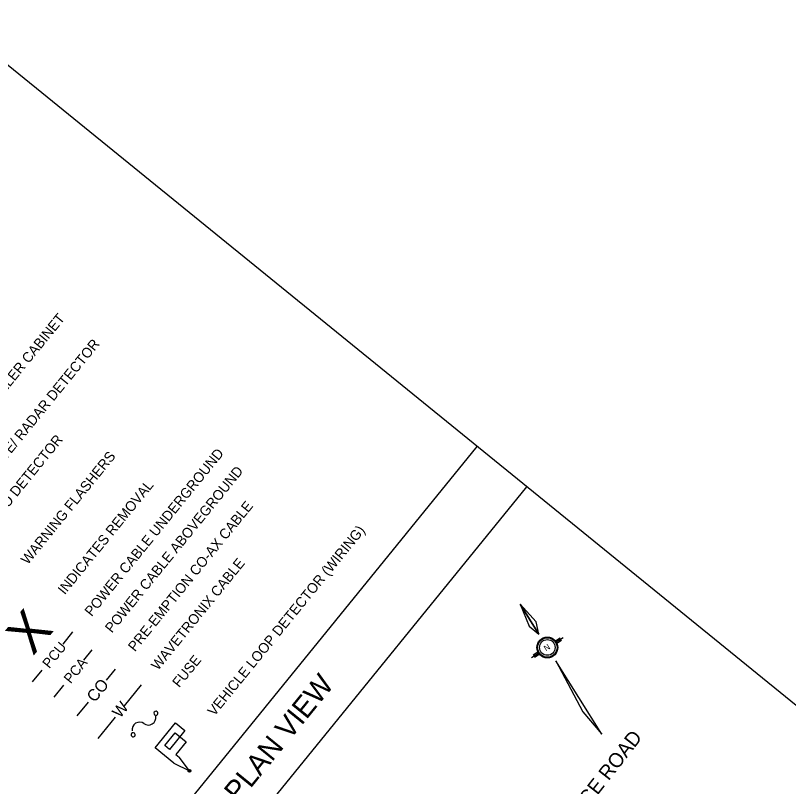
# Model space of a CAD drawing. Extents: x 592613 to 600223, y 4837996 to 4840103.
# Drawn here: x 592701.09 to 592734.31, y 4838961.75 to 4838994.9 of the extents above; entities that cross this region are included whole.
import ezdxf

# ---------------------------------------------------------------- set-up
doc = ezdxf.new("R2010")
doc.units = 0
for name, color, linetype in [('ENG_BORDER', 7, 'Continuous'), ('ENG_TITLEBLOCK', 7, 'Continuous'), ('ENG_TX_TITLEBLOCK', 7, 'Continuous'), ('Level 32', 7, 'Continuous'), ('Level 33', 7, 'Continuous'), ('TCS_FUSE', 7, 'Continuous'), ('TCS_LEGEND', 7, 'Continuous'), ('TCS_LOOP', 7, 'Continuous'), ('TCS_REMOVAL', 7, 'Continuous'), ('TCS_WR_CO', 7, 'Continuous'), ('TCS_WR_PCA', 7, 'Continuous'), ('TCS_WR_PCU', 7, 'Continuous'), ('TCS_WR_W', 7, 'Continuous')]:
    doc.layers.add(name, color=color, linetype=linetype)

msp = doc.modelspace()

# ---------------------------------------------------------------- linework, layer by layer
at = {"layer": 'ENG_BORDER'}
msp.add_line((592790.401, 4838919.927), (592686.018, 4839004.737), dxfattribs=at)
at = {"layer": 'ENG_TITLEBLOCK'}
msp.add_line((592695.53, 4838940.74), (592723.069, 4838974.634), dxfattribs=at)
msp.add_line((592695.53, 4838940.74), (592723.069, 4838974.634), dxfattribs=at)
msp.add_lwpolyline([(592693.395, 4838942.474), (592720.934, 4838976.368)], dxfattribs=at)
at = {"layer": 'ENG_TX_TITLEBLOCK'}
for p, q in [((592724.29, 4838968.017), (592724.494, 4838968.145)), ((592724.325, 4838967.968), (592724.63, 4838968.159)), ((592724.353, 4838967.915), (592724.558, 4838968.044)), ((592723.329, 4838967.416), (592723.534, 4838967.543)), ((592723.257, 4838967.299), (592723.562, 4838967.491)), ((592723.393, 4838967.314), (592723.597, 4838967.442))]:
    msp.add_line(p, q, dxfattribs=at)
for points in [[(592722.776, 4838969.594), (592723.161, 4838968.64), (592723.583, 4838968.305)], [(592722.776, 4838969.594), (592723.583, 4838968.305), (592723.466, 4838968.831)], [(592724.305, 4838967.153), (592725.468, 4838964.956), (592726.279, 4838964)]]:
    msp.add_lwpolyline(points, close=True, dxfattribs=at)
for radius in [0.45, 0.418, 0.336]:
    msp.add_circle((592723.944, 4838967.729), radius, dxfattribs=at)
at = {"layer": 'Level 32'}
for p, q in [((592724.29, 4838968.017), (592724.494, 4838968.145)), ((592724.325, 4838967.968), (592724.63, 4838968.159)), ((592724.353, 4838967.915), (592724.558, 4838968.044)), ((592723.329, 4838967.416), (592723.534, 4838967.543)), ((592723.257, 4838967.299), (592723.562, 4838967.491)), ((592723.393, 4838967.314), (592723.597, 4838967.442))]:
    msp.add_line(p, q, dxfattribs=at)
for points in [[(592722.776, 4838969.594), (592723.161, 4838968.64), (592723.583, 4838968.305)], [(592722.776, 4838969.594), (592723.583, 4838968.305), (592723.466, 4838968.831)], [(592724.305, 4838967.153), (592725.468, 4838964.956), (592726.279, 4838964)]]:
    msp.add_lwpolyline(points, close=True, dxfattribs=at)
for radius in [0.45, 0.418, 0.336]:
    msp.add_circle((592723.944, 4838967.729), radius, dxfattribs=at)
at = {"layer": 'TCS_FUSE'}
for centre, radius, start, end in [((592707.124, 4838964.899), 0.0867, 50.9061, 230.9061), ((592707.124, 4838964.899), 0.0867, 230.9061, 50.9061), ((592706.801, 4838964.713), 0.319, 233.6234, 10.2722), ((592706.423, 4838964.2), 0.319, 53.6234, 190.2722), ((592706.147, 4838963.978), 0.0867, 50.9061, 230.9061), ((592706.147, 4838963.978), 0.0867, 230.9061, 50.9061)]:
    msp.add_arc(centre, radius, start, end, dxfattribs=at)
at = {"layer": 'TCS_LOOP'}
for p, q in [((592707.089, 4838963.409), (592707.964, 4838964.486)), ((592707.964, 4838964.486), (592708.368, 4838964.158)), ((592707.51, 4838963.514), (592707.948, 4838964.053)), ((592708.368, 4838964.158), (592707.712, 4838963.35)), ((592707.948, 4838964.053), (592708.419, 4838963.67)), ((592708.419, 4838963.67), (592707.981, 4838963.131)), ((592707.897, 4838962.753), (592707.089, 4838963.409)), ((592707.712, 4838963.35), (592707.51, 4838963.514)), ((592707.981, 4838963.131), (592708.121, 4838963.018)), ((592708.569, 4838962.43), (592708.121, 4838963.018)), ((592707.897, 4838962.753), (592708.569, 4838962.43)), ((592708.512, 4838962.414), (592708.509, 4838962.435)), ((592708.516, 4838962.402), (592708.512, 4838962.447)), ((592708.521, 4838962.395), (592708.515, 4838962.455)), ((592708.525, 4838962.39), (592708.518, 4838962.461)), ((592708.529, 4838962.386), (592708.521, 4838962.466)), ((592708.533, 4838962.383), (592708.524, 4838962.47)), ((592708.537, 4838962.38), (592708.527, 4838962.473)), ((592708.541, 4838962.378), (592708.531, 4838962.476)), ((592708.545, 4838962.376), (592708.534, 4838962.479)), ((592708.548, 4838962.374), (592708.537, 4838962.481)), ((592708.552, 4838962.373), (592708.541, 4838962.483)), ((592708.556, 4838962.372), (592708.544, 4838962.485)), ((592708.56, 4838962.371), (592708.548, 4838962.486)), ((592708.563, 4838962.371), (592708.551, 4838962.487)), ((592708.567, 4838962.371), (592708.555, 4838962.488)), ((592708.571, 4838962.371), (592708.558, 4838962.489)), ((592708.574, 4838962.371), (592708.562, 4838962.49)), ((592708.578, 4838962.371), (592708.565, 4838962.49)), ((592708.581, 4838962.372), (592708.569, 4838962.49)), ((592708.585, 4838962.373), (592708.573, 4838962.49)), ((592708.588, 4838962.374), (592708.576, 4838962.489)), ((592708.592, 4838962.375), (592708.58, 4838962.489)), ((592708.595, 4838962.377), (592708.584, 4838962.488)), ((592708.599, 4838962.379), (592708.588, 4838962.487)), ((592708.602, 4838962.381), (592708.591, 4838962.486)), ((592708.606, 4838962.383), (592708.595, 4838962.484)), ((592708.609, 4838962.386), (592708.599, 4838962.482)), ((592708.612, 4838962.389), (592708.603, 4838962.479)), ((592708.615, 4838962.393), (592708.607, 4838962.476)), ((592708.619, 4838962.397), (592708.611, 4838962.473)), ((592708.622, 4838962.402), (592708.615, 4838962.468)), ((592708.625, 4838962.409), (592708.619, 4838962.462)), ((592708.627, 4838962.418), (592708.624, 4838962.454))]:
    msp.add_line(p, q, dxfattribs=at)
msp.add_circle((592708.569, 4838962.43), 0.0597, dxfattribs=at)
at = {"layer": 'TCS_WR_CO'}
for p, q in [((592704.996, 4838966.326), (592705.382, 4838966.8)), ((592703.747, 4838964.789), (592704.224, 4838965.375))]:
    msp.add_line(p, q, dxfattribs=at)
at = {"layer": 'TCS_WR_PCA'}
for p, q in [((592704.03, 4838967.187), (592704.387, 4838967.627)), ((592703.149, 4838966.102), (592702.735, 4838965.593))]:
    msp.add_line(p, q, dxfattribs=at)
at = {"layer": 'TCS_WR_PCU'}
for p, q in [((592703.134, 4838967.872), (592703.559, 4838968.395)), ((592702.227, 4838966.756), (592701.813, 4838966.247))]:
    msp.add_line(p, q, dxfattribs=at)
at = {"layer": 'TCS_WR_W'}
for p, q in [((592705.779, 4838965.223), (592706.512, 4838966.125)), ((592704.639, 4838963.82), (592705.387, 4838964.74))]:
    msp.add_line(p, q, dxfattribs=at)

# ---------------------------------------------------------------- texts
at = {"layer": 'ENG_TX_TITLEBLOCK'}
for s, height, rotation, p in [('N', 0.25, 32.0574, (592723.889, 4838967.559)), ('DETECTION ZONE - PLAN VIEW', 0.9, 50.9062, (592703.301, 4838951.94))]:
    msp.add_text(s, height=height, rotation=rotation, dxfattribs=at).set_placement(p)
at = {"layer": 'Level 32'}
msp.add_text('N', height=0.25, rotation=32.0574, dxfattribs=at).set_placement((592723.889, 4838967.559))
at = {"layer": 'Level 33'}
msp.add_text('REMEMBRANCE ROAD', height=0.61958, rotation=52.007, dxfattribs=at).set_placement((592722.413, 4838956.64))
at = {"layer": 'TCS_LEGEND'}
for s, height, p in [('TRAFFIC CONTROLLER CABINET', 0.43374, (592697.41, 4838974.681)), ('MICROWAVE/ RADAR DETECTOR', 0.43374, (592698.845, 4838973.515)), ('VIDEO DETECTOR', 0.43374, (592699.906, 4838972.653)), ('POWER CABLE UNDERGROUND', 0.43374, (592704.359, 4838969.035)), ('WARNING FLASHERS', 0.43374, (592701.619, 4838971.261)), ('POWER CABLE ABOVEGROUND', 0.43374, (592705.234, 4838968.324)), ('INDICATES REMOVAL', 0.43374, (592703.208, 4838969.97)), ('PRE-EMPTION CO-AX CABLE', 0.43374, (592706.224, 4838967.52)), ('VEHICLE LOOP DETECTOR (WIRING)', 0.43374, (592709.634, 4838964.749)), ('WAVETRONIX CABLE', 0.43374, (592707.214, 4838966.715)), ('FUSE', 0.4337, (592708.125, 4838965.975))]:
    msp.add_text(s, height=height, rotation=50.9061, dxfattribs=at).set_placement(p)
at = {"layer": 'TCS_REMOVAL'}
msp.add_text('X', height=1.631, rotation=50.9061, dxfattribs=at).set_placement((592701.842, 4838967.34))
at = {"layer": 'TCS_WR_CO'}
msp.add_text('CO', height=0.506, rotation=50.9061, dxfattribs=at).set_placement((592704.496, 4838965.336))
at = {"layer": 'TCS_WR_PCA'}
msp.add_text('PCA', height=0.4303, rotation=50.9061, dxfattribs=at).set_placement((592703.461, 4838966.146))
at = {"layer": 'TCS_WR_PCU'}
msp.add_text('PCU', height=0.4303, rotation=50.9061, dxfattribs=at).set_placement((592702.54, 4838966.799))
at = {"layer": 'TCS_WR_W'}
msp.add_text('W', height=0.495, rotation=50.9061, dxfattribs=at).set_placement((592705.586, 4838964.663))

doc.saveas('drawing.dxf')
